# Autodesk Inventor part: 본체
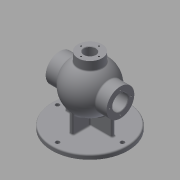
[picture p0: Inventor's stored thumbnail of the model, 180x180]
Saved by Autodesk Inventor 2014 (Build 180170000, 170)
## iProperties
Created: 2020-08
Part Number: 본체
Material: Generic
Document SubType Name: Modeling
Designer: kh
Density: 1 g/cm^3
Appearance: Default
Mass: 649.145 g
Surface Area: 1342.58 cm^2
Volume: 649.145 cm^3
Author: kh
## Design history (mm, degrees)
sketch "Sketch1"
  geometry: C1 r 85 at (0, 0); 1 further point
  constraints: 1 centre point, 1 coincident
  dimensions: "d0" = 170 diameter of C1
extrude "Extrusion1" new body sketch "Sketch1" distance "d1" = 10; taper "d2" = 0 deg
sketch "Sketch2" dims "d3" = 106
  geometry: L1 (77.464, 85)-(-77.464, 85); L2 (-85, 0)-(85, 0) reference; L3 (53, 85)-(-53, 85); A1 r 53 centre (0, 85) between (53, 85) and (-53, 85); 3 further points
  constraints: 4 end point, 2 coincident, 2 point on circle, 1 centre point, 1 horizontal, 1 horizontal alignment, 1 midpoint, 1 parallel, 1 point on line, 1 vertical alignment, 2 other
  dimensions: "d4" = 85 distance from line of L1.end L2
revolve "Revolution1" sketch "Sketch2" stored, may be unused: angle "d5" = 90 deg
workplane "Work Plane1"
sketch "Sketch3"
  geometry: L1 (0, 0)-(0, 85); C1 r 31 at (0, 85)
  constraints: 2 end point, 1 centre point, 1 coincident, 1 vertical
  dimensions: "d7" = 85 distance of L1.start L1.end; "d8" = 62 diameter of C1
extrude "Extrusion2" join sketch "Sketch3" stored distance "d9" = 10; taper "d10" = 0 deg
mirror "Mirror1"
workplane "Work Plane2"
sketch "Sketch4"
  geometry: L1 (-42.988, -31)-(-42.988, 31) reference; L2 (42.988, 31)-(42.988, -31) reference; C1 r 27 at (0, 0); 1 further point
  constraints: 1 centre point, 1 coincident
  dimensions: "d12" = 54 diameter of C1
extrude "Extrusion3" join sketch "Sketch4" stored distance "d13" = 10; taper "d14" = 0 deg
revolve "Revolution2" stored, may be unused: angle "d20" = 90 deg
sketch "Sketch6"
  geometry: C1 r 27 at (0, 0) reference; C2 r 13 at (0, 0)
  constraints: 1 centre point, 1 coincident
  dimensions: "d21" = 26 diameter of C2
extrude "Extrusion4" cut sketch "Sketch6" stored distance "d22" = 10; taper "d23" = 0 deg
sketch "Sketch9"
  geometry: L1 (52, -4)-(-52, -4); L2 (-52, -4)-(-52, 4); L3 (-52, 4)-(52, 4); L4 (52, 4)-(52, -4); L5 (52, -4)-(-52, 4); L6 (-52, -4)-(52, 4); C1 r 85 at (0, 0) reference
  constraints: 12 end point, 2 midpoint, 2 parallel, 1 horizontal, 1 perpendicular
  dimensions: "d26" = 8 distance of L1.end L2.end; "d27" = 104 distance of L2.end L3.end
extrude "Extrusion5" join sketch "Sketch9" stored distance "d28" = 10; taper "d29" = 0 deg
sketch "Sketch10"
  geometry: L1 (85, 10)-(-85, 10) reference; L2 (-43, 10)-(-43, 35.803); L3 (43, 10)-(43, 32.792); 1 further point
  constraints: 4 end point, 2 point on line, 1 parallel, 1 perpendicular
  dimensions: "d30" = 43 distance from line of point (0, 0) L2; "d31" = 86 distance between parallel lines of L3 L2
feature "Rib1" dims "d32" = 1, "d33" = 8, "d34" = 0, "d35" = 0, "d36" = 1, "d37" = 1
feature "Rib2" dims "d38" = 1, "d39" = 8, "d40" = 0, "d41" = 0, "d42" = 1, "d43" = 1
workplane "Work Plane3"
sketch "Sketch11"
  geometry: L1 (-19.151, -4.146)-(19.151, -4.146); L2 (19.151, -4.146)-(19.151, -13.854); L3 (19.151, -13.854)-(-19.151, -13.854); L4 (-19.151, -13.854)-(-19.151, -4.146); L5 (-19.151, -4.146)-(19.151, -13.854); L6 (-27, 0)-(-27, -19.393) reference; L7 (-27, 0)-(27, 0) reference; 2 further points
  constraints: 2 end point, 1 midpoint, 2 other
  dimensions: "d44" = 27 distance from line of point (0, -9) L6; "d45" = 9 distance from line of point (0, -9) L7
emboss "Emboss1" sketch "Sketch11" dims "d46" = 0.5, "d47" = 0
sketch "Sketch12" dims "d48" = 145
  geometry: C1 r 85 at (0, 0) reference; 2 further points
  constraints: 1 coincident, 1 vertical alignment, 2 other
hole "Hole1" sketch "Sketch12" at (0, 72.5) diameter "d49" = 9; stored, may be unused: countersink angle "d53" = 90 deg, drill point angle "d55" = 118 deg; dims "d50" = 6, "d51" = 4, "d52" = 2, "d54" = 8
pattern_circular "Circular Pattern1" dims angle "d57" = 360 deg
chamfer "Chamfer1" distance "d63" = 1; stored, may be unused: second distance "d64" = 2, angle "d65" = 45 deg
sketch "Sketch13" dims "d66" = 48
  geometry: 3 further points
  constraints: 1 horizontal alignment, 2 other
hole "Hole2" sketch "Sketch13" at (-24, 0) diameter "d67" = 3.242; stored, may be unused: countersink angle "d71" = 90 deg, drill point angle "d73" = 118 deg; dims "d68" = 12, "d69" = 4, "d70" = 2, "d72" = 15
pattern_circular "Circular Pattern2" dims angle "d75" = 360 deg
mirror "Mirror2"
sketch "Sketch14" dims "d77" = 40
  geometry: C1 r 14 at (0, 0) reference; 2 further points
  constraints: 1 coincident, 1 vertical alignment, 2 other
hole "Hole3" sketch "Sketch14" at (0, 20) diameter "d78" = 3.242; stored, may be unused: countersink angle "d82" = 90 deg, drill point angle "d84" = 118 deg; dims "d79" = 12, "d80" = 4, "d81" = 2, "d83" = 15
pattern_circular "Circular Pattern3" dims angle "d86" = 360 deg
fillet "Fillet1" dims "d88" = 3
fillet "Fillet2" dims "d89" = 3
fillet "Fillet3" dims "d90" = 3
chamfer "Chamfer2" distance "d96" = 1; stored, may be unused: second distance "d97" = 2, angle "d98" = 45 deg
body "Solid1"
node "Projected Loop1"
sketch "Sketch5"
  geometry: L1 (-42.988, 54)-(-68, 54) reference; L2 (-68, 54)-(-68, 116) reference; L3 (-68, 116)-(-42.988, 116) reference; L4 (-27, 130.607)-(-27, 150) reference; L5 (-27, 150)-(27, 150) reference; L6 (27, 150)-(27, 130.607) reference; L7 (42.988, 116)-(68, 116) reference; L8 (68, 116)-(68, 54) reference; L9 (68, 54)-(42.988, 54) reference; L10 (-85, 0)-(-85, 10) reference; L11 (-85, 10)-(85, 10) reference; L12 (85, 10)-(85, 0) reference; L13 (85, 0)-(-85, 0) reference; L14 (68, 102.5)-(68, 85); L15 (-68, 102.5)-(-68, 85); L16 (68, 85)-(-68, 85); L17 (-50.25, 102.5)-(-39.278, 102.5); L18 (68, 102.5)-(52, 102.5); L19 (52, 102.5)-(52, 103.5); L20 (52, 103.5)-(50.25, 103.5); L21 (50.25, 103.5)-(50.25, 102.5); L22 (50.25, 102.5)-(39.278, 102.5); L23 (-50.25, 102.5)-(-68, 102.5); A1 r 53 centre (0, 85) between (-42.988, 54) and (42.988, 54) reference; A2 r 53 centre (0, 85) between (-27, 130.607) and (-42.988, 116) reference; A3 r 53 centre (0, 85) between (42.988, 116) and (27, 130.607) reference; A4 r 43 centre (0, 85) between (39.278, 102.5) and (-39.278, 102.5); A5 r 43 centre (0, 85) between (39.278, 102.5) and (-39.278, 102.5); 1 further point
  constraints: 20 end point, 4 collinear, 4 point on circle, 3 parallel, 3 perpendicular, 2 centre point, 2 coincident, 2 midpoint, 2 point on line
  dimensions: "d15" = 86 diameter of A4; "d91" = 35 diameter of L18 L16; "d92" = 37 diameter of L20 L16; "d93" = 1.75 distance of L19.end L20.end; "d94" = 16 distance between parallel lines of L19 L8; "d95" = 35 diameter of L23 L16
node "Project Cut Edges1"
other parameters: "d6" = 68
